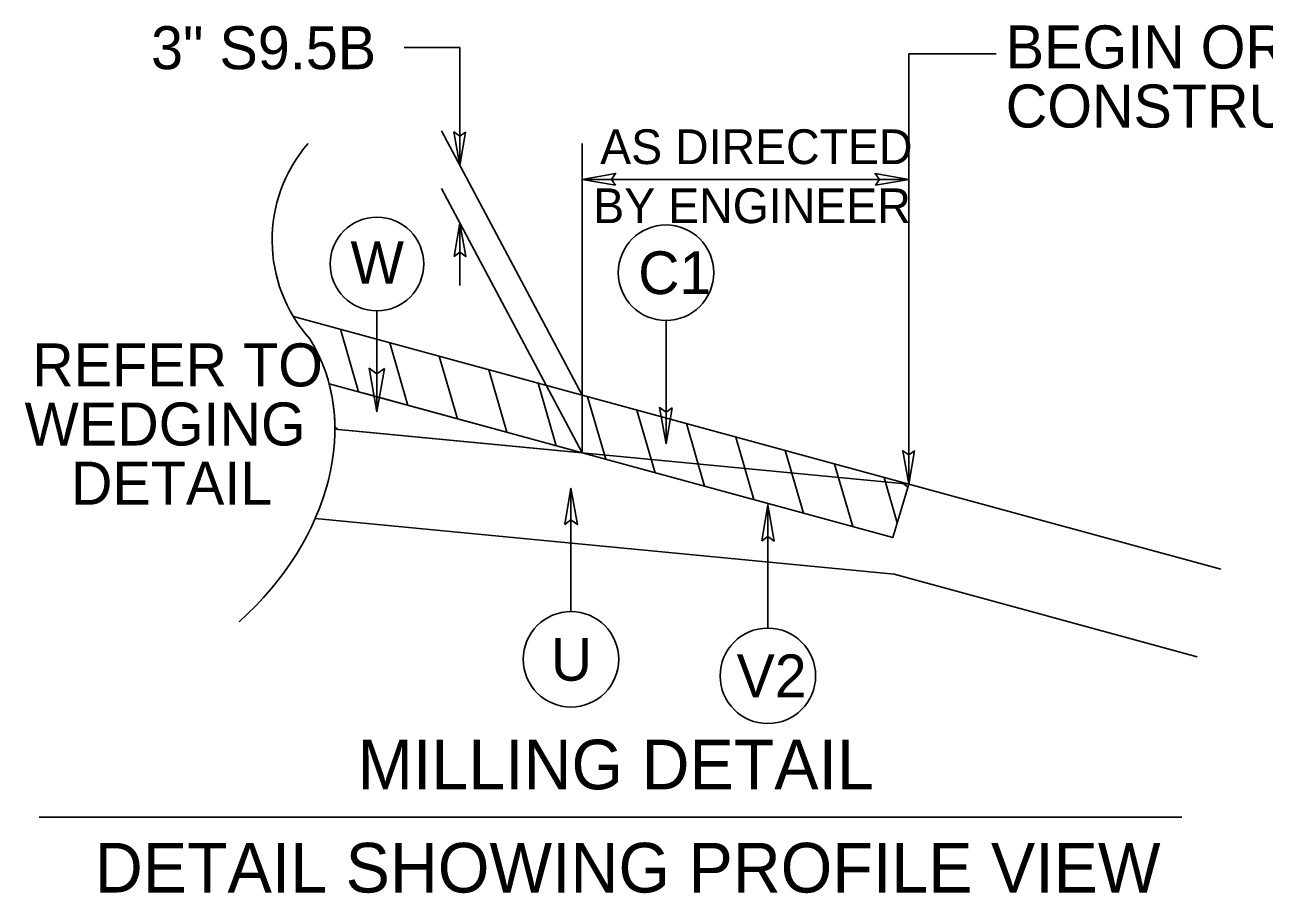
# Model space of a CAD drawing. Extents: x 1904401 to 1905163, y 193929 to 194736.
# Drawn here: x 1904982.52 to 1905019.98, y 194641.75 to 194668 of the extents above; entities that cross this region are included whole.
import ezdxf

# ---------------------------------------------------------------- set-up
doc = ezdxf.new("R2010")
doc.units = 0
for name, color, linetype in [('Old_Level_11', 7, 'Continuous'), ('Old_Level_19', 7, 'Continuous'), ('Old_Level_20', 7, 'Continuous'), ('Prop Lane Arrow CELL', 7, 'Continuous'), ('Prop Shade Medium', 7, 'Continuous'), ('Typical Detail Wedge2 CELL', 7, 'Continuous'), ('Typical ID Circle CELL', 7, 'Continuous'), ('Typical Text ID Circle CELL', 7, 'Continuous')]:
    doc.layers.add(name, color=color, linetype=linetype)

msp = doc.modelspace()

# ---------------------------------------------------------------- linework, layer by layer
at = {"layer": 'Old_Level_11'}
for p, q in [((1904993.162, 194659.351), (1904993.162, 194656.3)), ((1904982.953, 194644.042), (1905017.489, 194644.042))]:
    msp.add_line(p, q, dxfattribs=at)
for points in [[(1904995.839, 194664.751), (1904995.666, 194663.744), (1904995.486, 194664.756), (1904995.666, 194664.628)], [(1905000.369, 194663.149), (1904999.362, 194663.322), (1905000.375, 194663.501), (1905000.246, 194663.322)], [(1905008.224, 194663.149), (1905009.231, 194663.322), (1905008.218, 194663.501), (1905008.347, 194663.322)], [(1904995.492, 194660.996), (1904995.666, 194662.003), (1904995.845, 194660.99), (1904995.666, 194661.119)], [(1904993.387, 194657.609), (1904993.162, 194656.3), (1904992.929, 194657.616), (1904993.162, 194657.449)], [(1905002.085, 194656.422), (1905001.897, 194655.331), (1905001.703, 194656.428), (1905001.897, 194656.289)], [(1905009.404, 194655.116), (1905009.231, 194654.109), (1905009.052, 194655.122), (1905009.231, 194654.993)], [(1904998.837, 194652.895), (1904999.025, 194653.986), (1904999.219, 194652.889), (1904999.025, 194653.028)], [(1905004.788, 194652.396), (1905004.975, 194653.488), (1905005.17, 194652.39), (1905004.975, 194652.53)]]:
    msp.add_lwpolyline(points, close=True, dxfattribs=at)
msp.add_circle((1904993.161, 194660.765), 1.414, dxfattribs=at)
at = {"layer": 'Prop Lane Arrow CELL'}
for p, q in [((1904995.666, 194667.313), (1904993.981, 194667.313)), ((1904995.666, 194663.744), (1904995.666, 194667.313)), ((1905011.873, 194667.118), (1905009.231, 194667.118)), ((1905009.231, 194664.407), (1905009.231, 194667.118)), ((1904995.11, 194664.788), (1904999.362, 194656.799)), ((1904999.362, 194655.058), (1904999.362, 194664.407)), ((1905009.231, 194654.109), (1905009.231, 194664.407)), ((1905009.231, 194664.407), (1905009.231, 194664.407)), ((1905009.231, 194663.322), (1904999.362, 194663.322)), ((1904995.11, 194663.047), (1904999.362, 194655.058)), ((1904995.666, 194660.11), (1904995.666, 194662.003)), ((1905009.231, 194654.109), (1904990.635, 194659.177)), ((1904991.715, 194657.142), (1905008.757, 194652.497)), ((1904991.992, 194655.766), (1904991.888, 194655.85)), ((1904991.888, 194655.776), (1905009.231, 194654.109)), ((1905009.231, 194654.109), (1905008.757, 194652.497)), ((1905009.205, 194654.022), (1905009.03, 194654.164)), ((1905009.231, 194654.109), (1905018.666, 194651.538)), ((1904991.295, 194653.069), (1905008.789, 194651.387)), ((1905008.759, 194652.505), (1905008.738, 194652.503)), ((1905008.789, 194651.387), (1905017.945, 194648.892))]:
    msp.add_line(p, q, dxfattribs=at)
for centre, major_axis, ratio, start_param, end_param in [((1904994.469, 194661.479), (-2.812, 3.488), 0.998037, 0.180285, 1.621834), ((1904984.211, 194654.214), (6.925, 4.284), 0.773681, 4.938551, 6.283185)]:
    msp.add_ellipse(centre, major_axis=major_axis, ratio=ratio, start_param=start_param, end_param=end_param, dxfattribs=at)
at = {"layer": 'Prop Shade Medium'}
for p, q in [((1904991.888, 194655.85), (1904991.888, 194655.85)), ((1904991.888, 194655.85), (1904991.992, 194655.766)), ((1904991.992, 194655.766), (1904991.888, 194655.85)), ((1904991.888, 194655.776), (1904991.888, 194655.776)), ((1904991.888, 194655.776), (1904991.992, 194655.766))]:
    msp.add_line(p, q, dxfattribs=at)
for points in [[(1904992.766, 194656.856), (1904992.605, 194656.899), (1904991.715, 194657.142)], [(1904992.744, 194655.694), (1904999.363, 194655.058), (1904992.766, 194656.856)], [(1904991.992, 194655.766), (1904991.992, 194655.766), (1904992.744, 194655.694)]]:
    msp.add_lwpolyline(points, dxfattribs=at)
for start_param, end_param in [(5.849468, 6.049581), (5.838341, 5.849468)]:
    msp.add_ellipse((1904984.211, 194654.214), major_axis=(6.925, 4.284), ratio=0.773681, start_param=start_param, end_param=end_param, dxfattribs=at)
at = {"layer": 'Typical Detail Wedge2 CELL'}
for p, q in [((1904992.056, 194658.79), (1904992.605, 194656.899)), ((1904993.55, 194658.383), (1904994.099, 194656.492)), ((1904995.044, 194657.976), (1904995.592, 194656.085)), ((1904996.538, 194657.569), (1904997.086, 194655.678)), ((1904998.031, 194657.162), (1904998.58, 194655.271)), ((1904999.525, 194656.754), (1905000.074, 194654.864)), ((1905001.019, 194656.347), (1905001.568, 194654.457)), ((1905002.513, 194655.94), (1905003.061, 194654.05)), ((1905004.007, 194655.533), (1905004.555, 194653.643)), ((1905005.5, 194655.126), (1905006.049, 194653.235)), ((1905006.994, 194654.719), (1905007.543, 194652.828)), ((1905008.488, 194654.312), (1905008.886, 194652.938))]:
    msp.add_line(p, q, dxfattribs=at)
at = {"layer": 'Typical ID Circle CELL'}
for p, q in [((1905001.897, 194659.059), (1905001.897, 194655.331)), ((1904999.025, 194650.258), (1904999.025, 194653.986)), ((1905004.975, 194649.759), (1905004.975, 194653.488))]:
    msp.add_line(p, q, dxfattribs=at)
for centre in [(1905001.897, 194660.502), (1904999.025, 194648.816), (1905004.975, 194648.317)]:
    msp.add_circle(centre, 1.443, dxfattribs=at)

# ---------------------------------------------------------------- texts
at = {"layer": 'Old_Level_19'}
for s, p in [('MILLING DETAIL', (1904992.575, 194644.886)), ('DETAIL SHOWING PROFILE VIEW', (1904984.634, 194641.768))]:
    msp.add_text(s, height=1.5, dxfattribs=at).set_placement(p)
at = {"layer": 'Old_Level_20'}
msp.add_text('W', height=1.279, dxfattribs=at).set_placement((1904992.362, 194660.167))
at = {"layer": 'Prop Lane Arrow CELL'}
for s, height, p in [('3" S9.5B', 1.3, (1904986.333, 194666.652)), ('BEGIN OR END', 1.3, (1905012.164, 194666.676)), ('CONSTRUCTION', 1.3, (1905012.164, 194664.889)), ('AS DIRECTED', 1.05, (1904999.907, 194663.785)), ('BY ENGINEER', 1.05, (1904999.699, 194662)), ('REFER TO', 1.3, (1904982.739, 194657.065)), ('WEDGING', 1.3, (1904982.51, 194655.278)), ('DETAIL', 1.3, (1904983.911, 194653.491))]:
    msp.add_text(s, height=height, dxfattribs=at).set_placement(p)
at = {"layer": 'Typical Text ID Circle CELL'}
for s, height, p in [('C1', 1.2912, (1905001.056, 194659.856)), ('U', 1.291, (1904998.416, 194648.17)), ('V2', 1.2912, (1905004.033, 194647.672))]:
    msp.add_text(s, height=height, dxfattribs=at).set_placement(p)

doc.saveas('drawing.dxf')
